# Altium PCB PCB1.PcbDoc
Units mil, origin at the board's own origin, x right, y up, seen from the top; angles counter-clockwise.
Board outline 3937.01 x 3937.01 mil, 2 copper layers (Top Layer, Bottom Layer); 21 components, 31 nets, 128 pads, 5 vias.
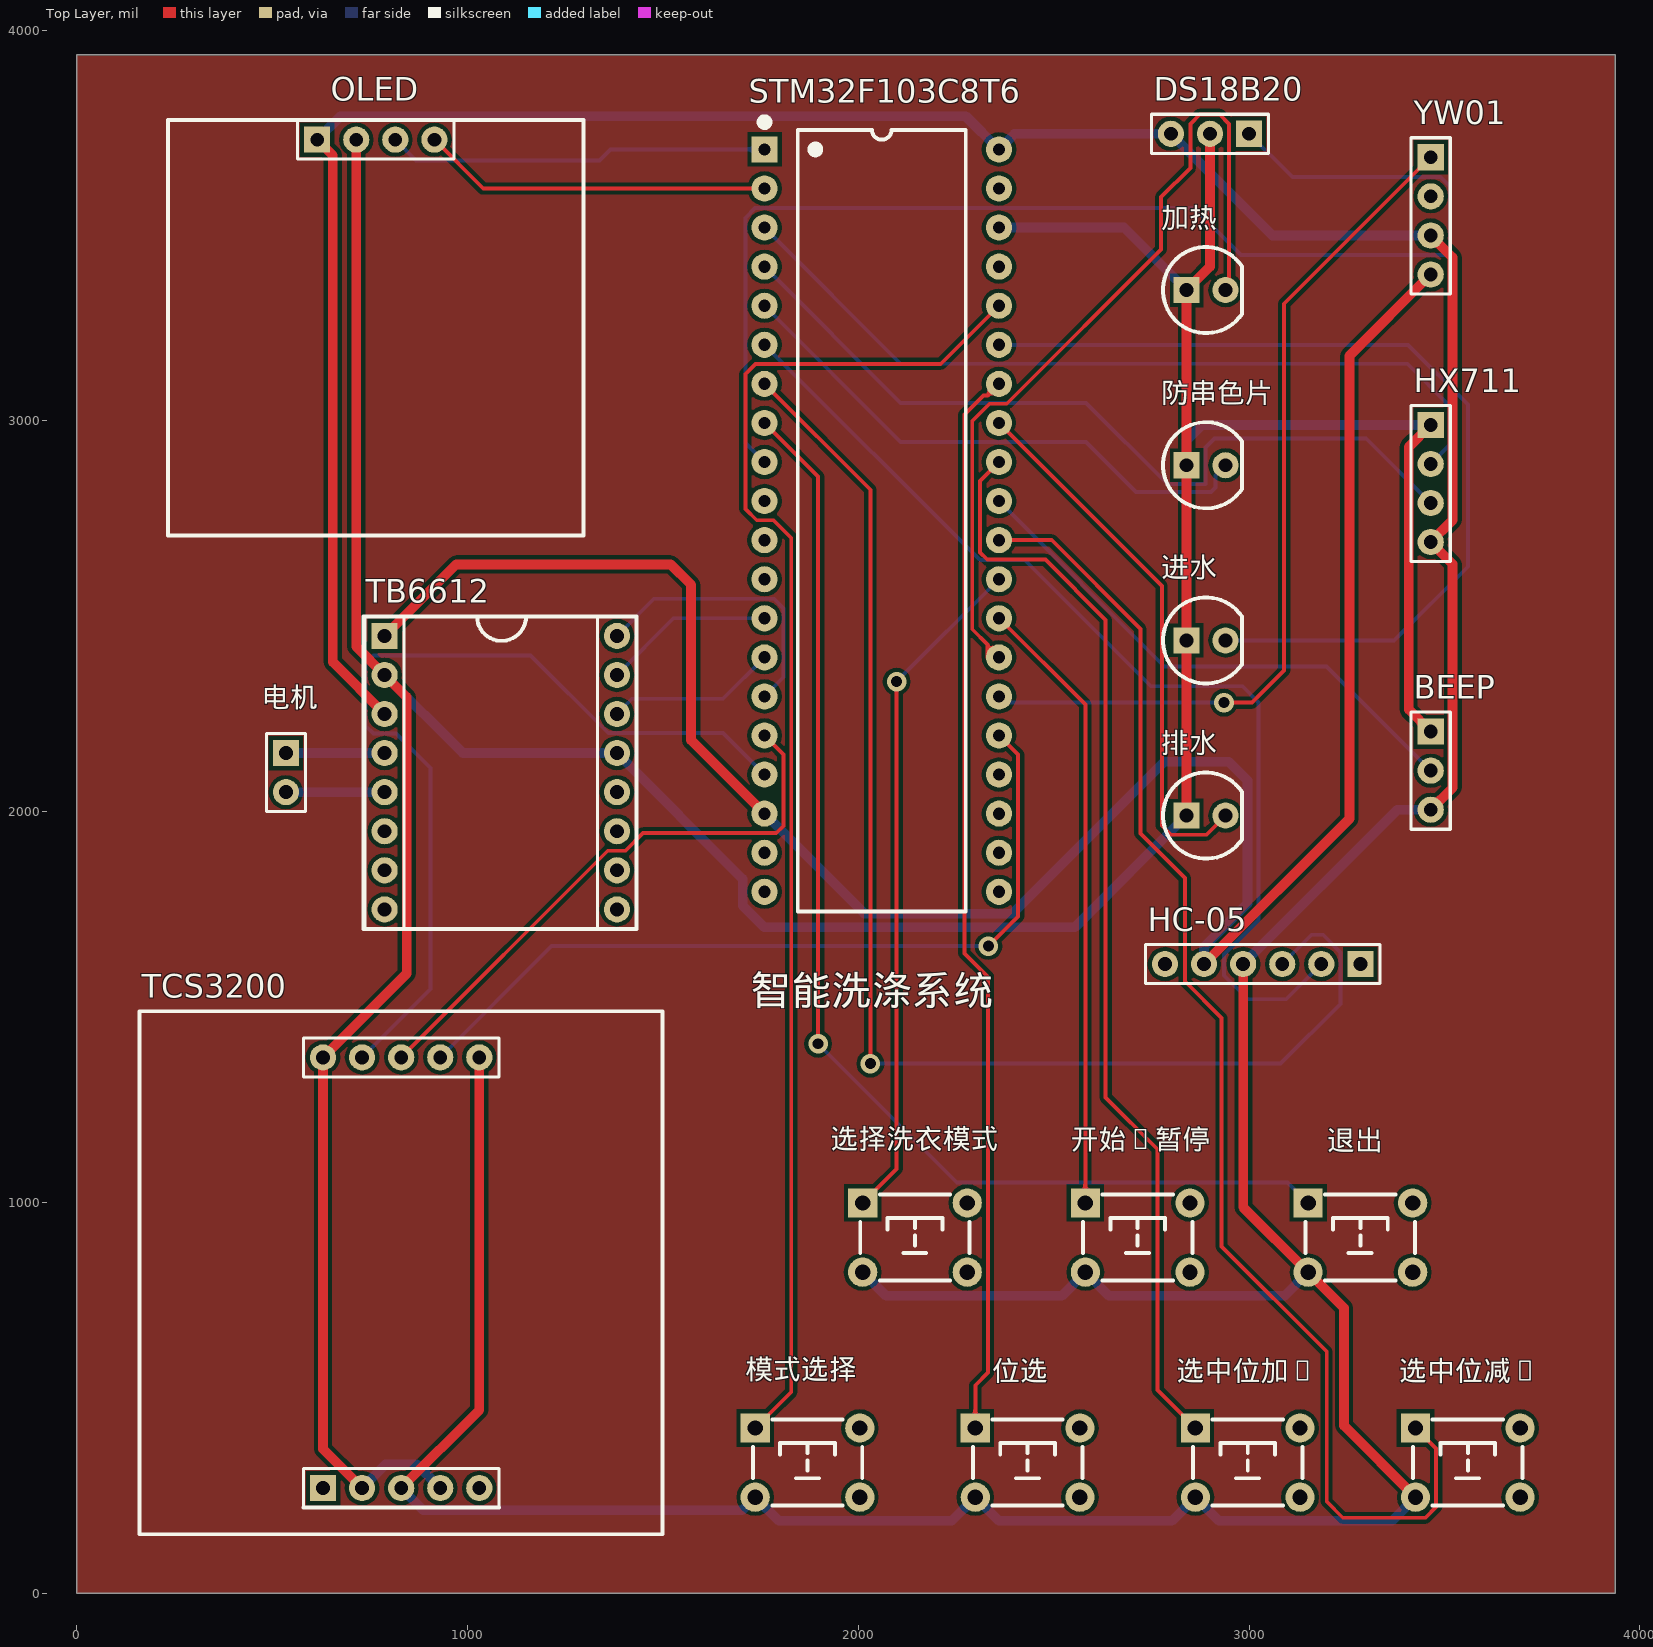
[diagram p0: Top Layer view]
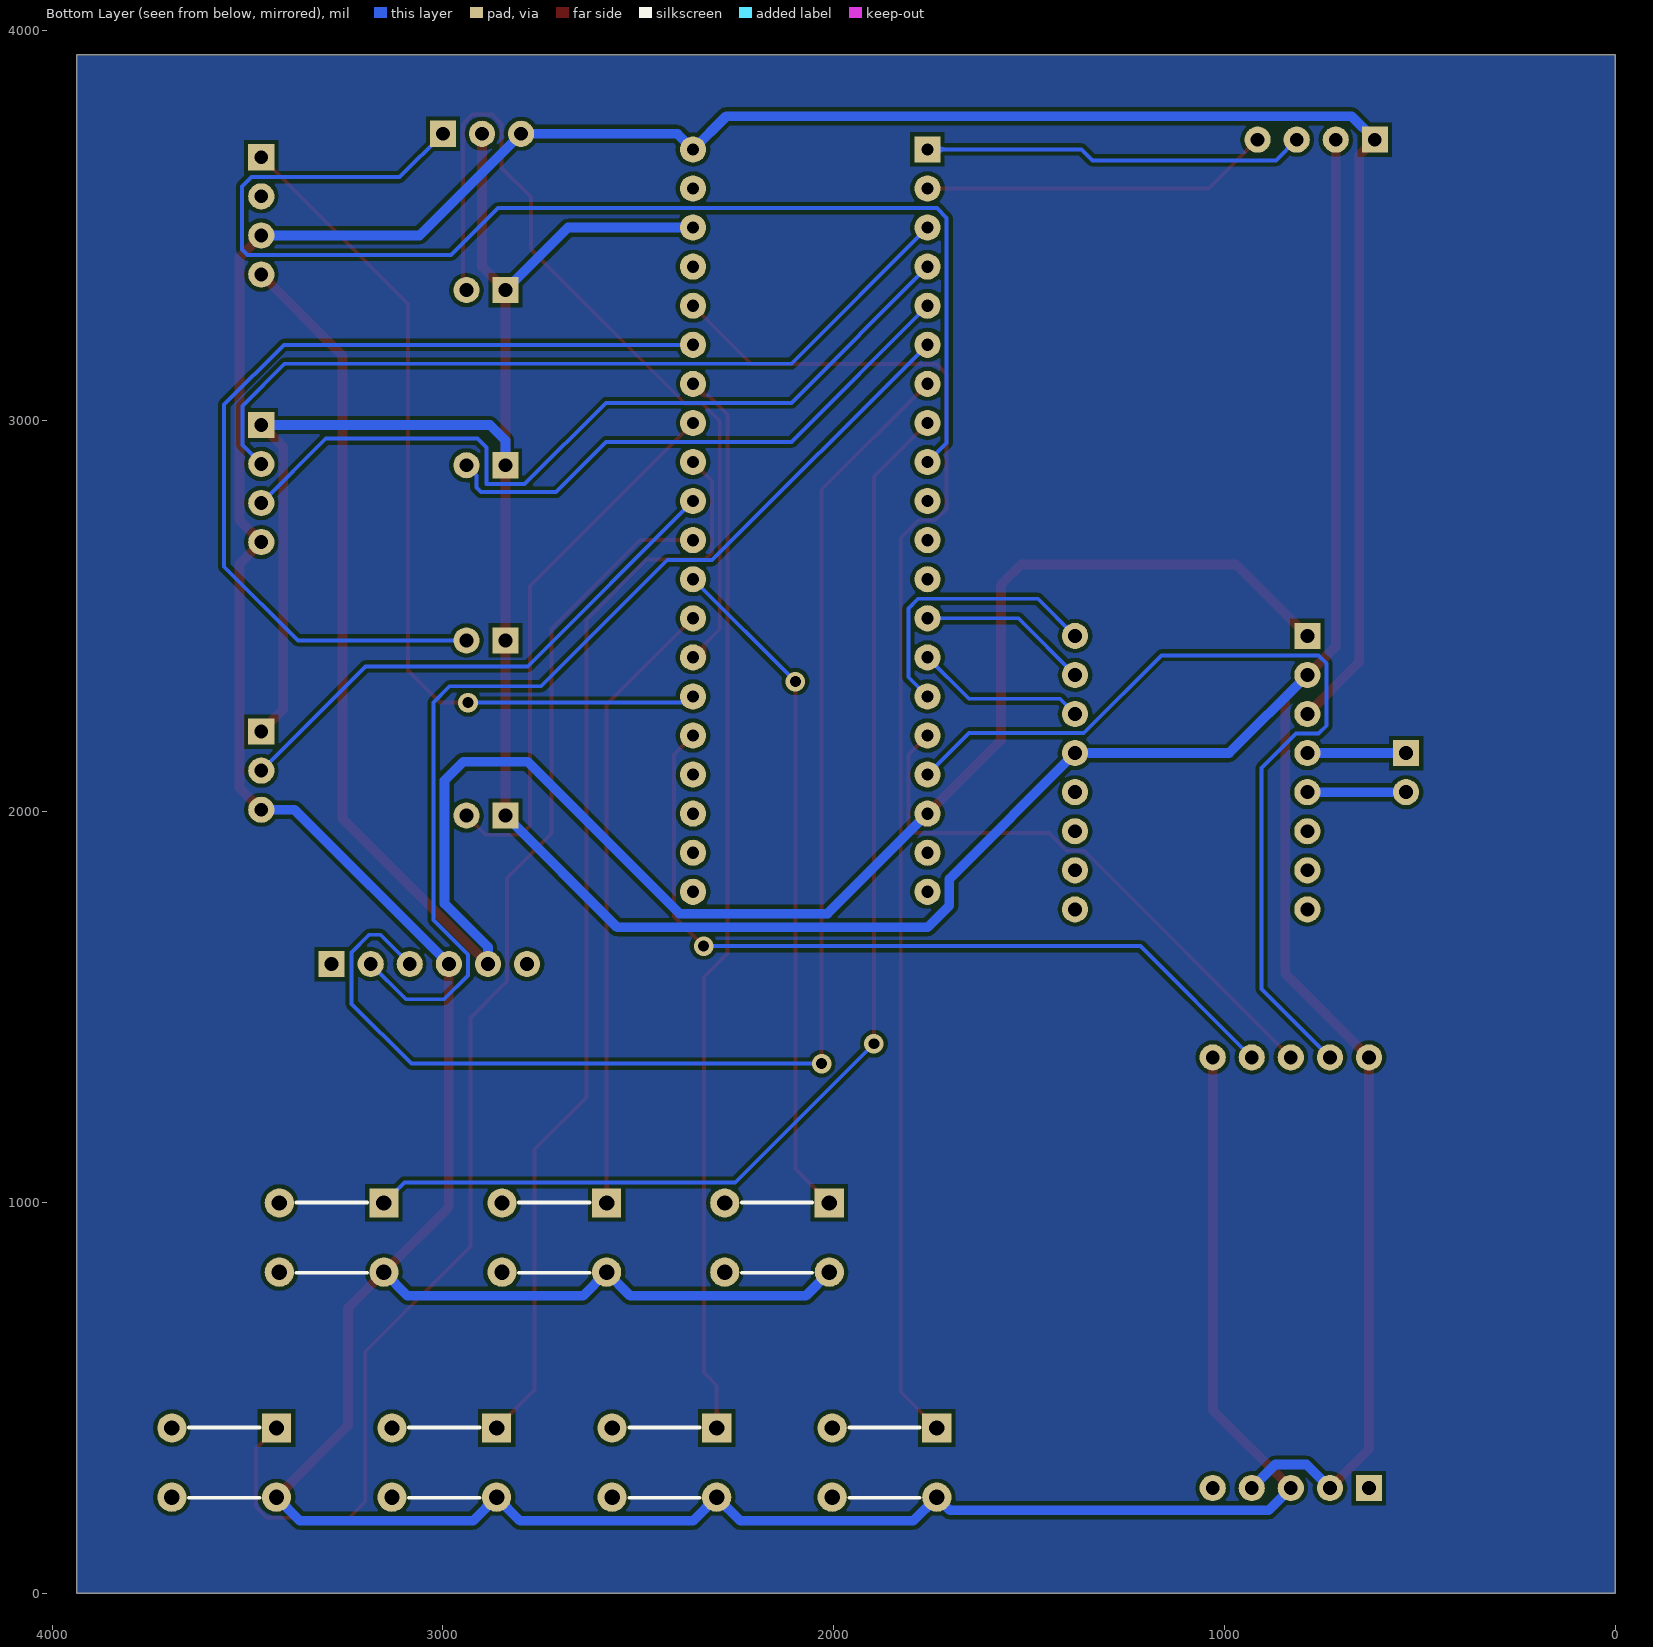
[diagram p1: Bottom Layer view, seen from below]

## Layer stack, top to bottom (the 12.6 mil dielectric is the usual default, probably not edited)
Top Solder: solder mask 0.4, Solder Resist, Dk 3.5
Top Layer: signal copper 1.4
Dielectric 1: dielectric 12.6, FR-4, Dk 4.8
Bottom Layer: signal copper 1.4
Bottom Solder: solder mask 0.4, Solder Resist, Dk 3.5

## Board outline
0,0 0,3937.01 3937.01,3937.01 3937.01,0

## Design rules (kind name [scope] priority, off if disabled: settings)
Clearance [All] p1: gap=10 ignorepadtopadclearanceinfootprint=FALSE except(0: Arc-Hole Track-Hole SMDPad-Hole THPad-Hole Via-Hole Fill-Hole Poly-Hole Region-Hole Text-Hole)
PolygonConnect [All] p1: connectstyle=Relief reliefconductorwidth=10 reliefentries=4 polygonreliefangle="90 Angle" airgapwidth=10
RoutingVias [All] p1: holewidth=28 width=50 viastyle="Through Hole" minholewidth=28 minwidth=50 maxholewidth=28 maxwidth=50
SolderMaskExpansion [All] p1: expansion=4
Width Width_Power_All [InNetClass('Power_All Nets')] p1: maxlimit=30 minlimit=20 preferedwidth=25 minimp=50.000000 maximp=50.000000 favimp=50.000000
Width [All] p2: maxlimit=10 minlimit=10 preferedwidth=10
30 further rules are at their usual default settings.

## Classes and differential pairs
net class "Power_All Nets": 3V3 5V GND NetB1_1 NetB1_2

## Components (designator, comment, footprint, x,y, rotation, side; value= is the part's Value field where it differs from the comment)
BEEP "BEEP" HDR2.54-M-LI-3P 3465,2105 r270 top
DS18B20 "?" HDR2.54-M-LI-3P 2900,3735 r180 top
HC-05 "HC-05" HDR2.54-M-LI-6P 3035,1610 r180 top
HX711 "HX711" HDR2.54-M-LI-4P 3465,2840 r270 top (schematic designator *)
OLED "OLED0.96" HDR2.54-M-LI-4P 765,3720 r0 top
STM32F103C8T6 "STM32F103C8T6" DIP40-600_MH 2060,2745 r0 top (schematic designator P1)
TB6612 "TB6612" HDR2.54-M-LI-8*2P 1085,2100 r270 top (schematic designator P2)
TCS3200 "TCS3200" HDR2.54-M-LI-5*2P 830,820 r0 top (schematic designator P3)
YW01 "YW01" HDR2.54-M-LI-4P 3465,3525 r270 top
位选 "TSW DIP-6x6" "TSW DIP-6*6*6" 2433.33,334 r0 top (schematic designator λѡ)
加热 "加热" "LED 5MM-R" 2890,3335 r0 top (schematic designator D1)
开始/暂停 "TSW DIP-6x6" "TSW DIP-6*6*6" 2715,910 r0 top
排水 "排水" "LED 5MM-R" 2890,1990 r0 top (schematic designator D4)
模式选择 "TSW DIP-6x6" "TSW DIP-6*6*6" 1870,334 r0 top
电机 "Motor" HDR2.54-LI-2P 535,2100 r270 top (schematic designator B1)
进水 "进水" "LED 5MM-R" 2890,2438.33 r0 top (schematic designator D3)
退出 "TSW DIP-6x6" "TSW DIP-6*6*6" 3285,910 r0 top
选中位减1 "TSW DIP-6x6" "TSW DIP-6*6*6" 3560,334 r0 top
选中位加1 "TSW DIP-6x6" "TSW DIP-6*6*6" 2996.67,334 r0 top
选择洗衣模式 "TSW DIP-6x6" "TSW DIP-6*6*6" 2145,910 r0 top
防串色片 "串色片" "LED 5MM-R" 2890,2886.67 r0 top (schematic designator D2)

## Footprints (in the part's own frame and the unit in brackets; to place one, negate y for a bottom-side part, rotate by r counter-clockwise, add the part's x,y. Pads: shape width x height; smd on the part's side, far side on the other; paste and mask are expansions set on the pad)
DIP40-600_MH [mm] "带底座 52*15.2*4mm(长宽高)"
  rect 1.7x1.7 hole 0.8: 1(-7.62,24.13)
  round 1.7 hole 0.8: 2(-7.62,21.59) 3(-7.62,19.05) 4(-7.62,16.51) 5(-7.62,13.97) 6(-7.62,11.43) 7(-7.62,8.89) 8(-7.62,6.35) 9(-7.62,3.81) 10(-7.62,1.27) 11(-7.62,-1.27) 12(-7.62,-3.81) 13(-7.62,-6.35) 14(-7.62,-8.89) 15(-7.62,-11.43) 16(-7.62,-13.97) 17(-7.62,-16.51) 18(-7.62,-19.05) 19(-7.62,-21.59) 20(-7.62,-24.13) 21(7.62,-24.13) 22(7.62,-21.59) 23(7.62,-19.05) 24(7.62,-16.51) 25(7.62,-13.97) 26(7.62,-11.43) 27(7.62,-8.89) 28(7.62,-6.35) 29(7.62,-3.81) 30(7.62,-1.27) 31(7.62,1.27) 32(7.62,3.81) 33(7.62,6.35) 34(7.62,8.89) 35(7.62,11.43) 36(7.62,13.97) 37(7.62,16.51) 38(7.62,19.05) 39(7.62,21.59) 40(7.62,24.13)
  silkscreen extent -7.87,-25.4 5.46,26.16, body extent -8.9,-26.18 8.9,26.18, height 8.3
HDR2.54-LI-2P [mm] "封装库来自淘宝卖家 ID：黄晶宝石"
  rect 1.7x1.7 hole 0.9: 1(-1.27,0)
  round 1.7 hole 0.9: 2(1.27,0)
  silkscreen extent -2.54,-1.27 2.54,1.27, body extent -2.54,-1.27 2.54,1.27, height 8.5
HDR2.54-M-LI-3P [mm] "排母，3脚   淘宝ID:黄晶宝石   店铺网址:https://shop463601444.taobao.com"
  rect 1.7x1.7 hole 0.9: 1(-2.54,0)
  round 1.7 hole 0.9: 2(0,0) 3(2.54,0)
  silkscreen extent -3.81,-1.27 3.81,1.27, body extent -3.81,-1.27 3.81,1.27, height 8.5
HDR2.54-M-LI-4P [mm] "排母，4脚  淘宝ID:黄晶宝石   店铺网址:https://shop463601444.taobao.com"
  rect 1.7x1.7 hole 0.9: 1(-3.81,0)
  round 1.7 hole 0.9: 2(-1.27,0) 3(1.27,0) 4(3.81,0)
  silkscreen extent -5.08,-1.27 5.08,1.27, body extent -5.08,-1.27 5.08,1.27, height 8.5
HDR2.54-M-LI-5*2P [mm]
  rect 1.7x1.7 hole 0.9: 1(-5.08,-14)
  round 1.7 hole 0.9: 2(-2.54,-14) 3(0,-14) 4(2.54,-14) 5(5.08,-14) 6(-5.08,14) 7(-2.54,14) 8(0,14) 9(2.54,14) 10(5.08,14)
  silkscreen extent -17,-17 17,17, body extent -6.35,-15.27 6.35,15.27, height 8.5
HDR2.54-M-LI-6P [mm] "排母，6脚  淘宝ID:黄晶宝石   店铺网址:https://shop463601444.taobao.com"
  rect 1.7x1.7 hole 0.9: 1(-6.35,0)
  round 1.7 hole 0.9: 2(-3.81,0) 3(-1.27,0) 4(1.27,0) 5(3.81,0) 6(6.35,0)
  silkscreen extent -7.62,-1.27 7.62,1.27, body extent -7.62,-1.27 7.62,1.27, height 8.5
HDR2.54-M-LI-8*2P [mm] "排母，8*2脚"
  rect 1.7x1.7 hole 0.9: 1(-8.89,-7.55)
  round 1.7 hole 0.9: 2(-6.35,-7.55) 3(-3.81,-7.55) 4(-1.27,-7.55) 5(1.27,-7.55) 6(3.81,-7.55) 7(6.35,-7.55) 8(8.89,-7.55) 9(-8.89,7.55) 10(-6.35,7.55) 11(-3.81,7.55) 12(-1.27,7.55) 13(1.27,7.55) 14(3.81,7.55) 15(6.35,7.55) 16(8.89,7.55)
  silkscreen extent -10.16,-8.92 10.16,8.82, body extent -10.16,-8.82 10.16,8.82, height 8.5
"LED 5MM-R" [mm] "红色5mm直插LED"
  rect 1.7x1.7 hole 0.9: 1(-1.27,0)
  round 1.7 hole 0.9: 2(1.27,0)
  silkscreen extent -2.8,-2.8 2.33,2.8, body extent -2.85,-2.85 2.45,2.85, height 8.75
"TSW DIP-6*6*6" [mm] "6*6*6mm"
  rect 1.9x1.9 hole 1: 1(-3.4,2.25)
  round 1.9 hole 1: 2(-3.4,-2.25) 3(3.4,-2.25) 4(3.4,2.25)
  silkscreen extent -3.56,-2.79 3.56,2.79, body extent -4.11,-3 4.11,3, height 5.95

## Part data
BEEP: "BEEP, 3-Pin"
DS18B20: library part DS18B20, "DS18B20, 3-Pin"
HC-05: "HC-05, 6-Pin"
HX711: "HX711,4-Pin"
OLED: library part OLED, "OLED0.96,4-Pin"
STM32F103C8T6: "最小系统板"
TB6612: library part TB66612, "TB66612,16-Pin"
TCS3200: library part PCS3200, "PCS3200, 10-Pin, Dual row"
YW01: "YW01,4-Pin"
位选 开始/暂停 模式选择 退出 选中位减1 选中位加1 选择洗衣模式: "直插6*6*5轻触开关"
加热 排水 进水 防串色片: library part LED, "Typical INFRARED GaAs LED"
电机: "Motor, General Kind"

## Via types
v1: diameter 50, hole 28, Top Layer to Bottom Layer, 5 vias

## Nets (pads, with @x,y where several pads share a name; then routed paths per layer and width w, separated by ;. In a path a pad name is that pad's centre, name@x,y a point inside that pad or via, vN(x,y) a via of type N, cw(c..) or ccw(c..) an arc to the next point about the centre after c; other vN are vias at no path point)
3V3: BEEP.1 DS18B20.2 HX711.1 OLED.2 STM32F103C8T6.38 TB6612.2 TB6612.12 TCS3200.2 TCS3200.4 TCS3200.6 加热.1 排水.1 进水.1 防串色片.1 | length 10215.2
  Top Layer w25: OLED.2 715,2422.76 TB6612.2 844,2293.76 844,1585.18 TCS3200.6 630,368.82 TCS3200.2 ; 排水.1 进水.1 防串色片.1 加热.1 2900,3395 DS18B20.2 ; BEEP.1 3409,2261 3409,2934 HX711.1
  Bottom Layer w25: TCS3200.2 790.18,329 869.82,329 TCS3200.4 ; TB6612.2 987.76,2150 TB6612.12 1704,1828.24 1704,1760 1759.97,1704.03 2554.03,1704.03 排水.1 ; STM32F103C8T6.38 2680,3495 加热.1 ; 防串色片.1 2840,2950 2880,2990 HX711.1
5V: HC-05.5 STM32F103C8T6.18 TB6612.1 YW01.4 | length 5589.7
  Top Layer w25: TB6612.1 970.76,2633 1520,2633 1572,2581 1572,2183 STM32F103C8T6.18 ; HC-05.5 3257,1982 3257,3167 YW01.4
  Bottom Layer w25: STM32F103C8T6.18 2015.97,1739.03 2395.03,1739.03 2784,2128 2948,2128 2996,2080 2996,1764.57 2885,1653.57 HC-05.5
GND: BEEP.3 DS18B20.3 HC-05.4 HX711.4 OLED.1 STM32F103C8T6.40 TB6612.3 TCS3200.3 TCS3200.10 YW01.3 位选.2 开始/暂停.2 模式选择.2 退出.2 选中位减1.2 选中位加1.2 选择洗衣模式.2 | length 13538.6
  Top Layer w25: OLED.1 655,3680 655,2382.76 TB6612.3 ; TCS3200.3 1030,468.82 TCS3200.10 ; HC-05.4 2985,987.56 退出.2 3243,729.56 3243,428.56 选中位减1.2 ; BEEP.3 3521,2061 3521,2634 HX711.4 3521,2746 3521,3419 YW01.3
  Bottom Layer w25: OLED.1 675,3780 2275,3780 STM32F103C8T6.40 2400,3735 DS18B20.3 3060,3475 YW01.3 ; TCS3200.3 886.82,212 1702.72,212 模式选择.2 1796.56,185 2239.06,185 位选.2 2359.89,185 2802.39,185 选中位加1.2 2923.23,185 3365.72,185 选中位减1.2 ; 选择洗衣模式.2 2071.56,761 2520.72,761 开始/暂停.2 2641.56,761 3090.72,761 退出.2 ; HC-05.4 3380,2005 BEEP.3
NetB1_1: TB6612.4 电机.1 | length 254.8
  Bottom Layer w25: 电机.1@535,2145 540,2150 TB6612.4
NetB1_2: TB6612.5 电机.2 | length 254.8
  Bottom Layer w25: 电机.2@535,2045 540,2050 TB6612.5
PA0: STM32F103C8T6.25 TCS3200.9 | length 2111.8
  Top Layer w10: v1(2333,1656) 2409,1732 2409,2146 STM32F103C8T6.25
  Bottom Layer w10: TCS3200.9 1214.82,1656 v1(2333,1656)
PA1: STM32F103C8T6.26 YW01.1 | length 2249.3
  Top Layer w10: v1(2936,2279) 3008,2279 3090,2361 3090,3300 YW01.1
  Bottom Layer w10: STM32F103C8T6.26 2360,2279 v1(2936,2279)
PA2: STM32F103C8T6.27 加热.2 | length 2215.3
  Top Layer w10: STM32F103C8T6.27 2331,2395 2331,2427.53 2291.53,2467 2291.53,3000 2335.53,3044 2380,3044 2775,3439 2775,3573 2850,3648 2850,3760 2874,3784 2925,3784 2949,3760 2949,3344 加热.2
PA3: STM32F103C8T6.28 开始/暂停.1 | length 1588
  Top Layer w10: STM32F103C8T6.28 2581.14,2273.86 开始/暂停.1
PA4: STM32F103C8T6.29 选择洗衣模式.1 | length 1740.9
  Top Layer w10: 选择洗衣模式.1 2098,1085.44 v1(2098,2333)
  Bottom Layer w10: v1(2098,2333) STM32F103C8T6.29
PA5: STM32F103C8T6.30 选中位减1.1 | length 3420.2
  Top Layer w10: STM32F103C8T6.30 2495,2695 2722,2468 2722,1944 2836,1830 2836,1566 2930,1472 2930,887 3199,618 3199,234 3240,193 3452,193 3479,220 3479,369.72 选中位减1.1
PA6: BEEP.2 STM32F103C8T6.31 | length 1390.8
  Bottom Layer w10: STM32F103C8T6.31 2783,2372 3198,2372 BEEP.2
PA7: STM32F103C8T6.32 选中位加1.1 | length 2808.1
  Top Layer w10: STM32F103C8T6.32 2311.53,2846.53 2311.53,2663.47 2330,2645 2479,2645 2633,2491 2633,1269 2766,1136 2766,519.39 选中位加1.1
PA8: STM32F103C8T6.5 防串色片.2 | length 1424.1
  Bottom Layer w10: STM32F103C8T6.5 2108.47,2946.53 2582.47,2946.53 2710.8,2818.2 2902.67,2818.2 2914.47,2830 2914.47,2861.13 防串色片.2
PA9: HC-05.2 STM32F103C8T6.6 | length 2690
  Bottom Layer w10: STM32F103C8T6.6 2311,2644 2426,2644 2749,2321 2983,2321 3024,2280 3024,1722.47 2936,1634.47 2936,1581 2997,1520 3095,1520 HC-05.2
PA10: HC-05.3 STM32F103C8T6.7 | length 3449.3
  Top Layer w10: STM32F103C8T6.7 2031,2824 v1(2031,1355)
  Bottom Layer w10: v1(2031,1355) 3081,1355 3234,1508 3234,1640 3189,1685 3160,1685 HC-05.3
PA11: STM32F103C8T6.8 退出.1 | length 3068.6
  Top Layer w10: STM32F103C8T6.8 1897,2858 v1(1897,1406)
  Bottom Layer w10: v1(1897,1406) 2252,1051 3098.72,1051 退出.1
PA12: DS18B20.1 STM32F103C8T6.9 | length 3245.1
  Bottom Layer w10: STM32F103C8T6.9 1711,2944 1711,3520 1736,3545 2859,3545 2979,3425 3500,3425 3514,3439 3514,3600 3490,3624 3111,3624 DS18B20.1
PB0: STM32F103C8T6.33 排水.2 | length 1396.6
  Top Layer w10: STM32F103C8T6.33 2777,2578 2777,1964 2800,1941 2891,1941 排水.2
PB1: STM32F103C8T6.34 位选.1 | length 2753.4
  Top Layer w10: 位选.1 2299.48,532 2332,564.52 2332,1577 2271.53,1637.47 2271.53,3016.42 2320,3064.88 2329.88,3064.88 STM32F103C8T6.34
PB5: STM32F103C8T6.13 TB6612.10 | length 437.8
  Bottom Layer w10: TB6612.10 1527.24,2495 STM32F103C8T6.13
PB6: STM32F103C8T6.14 TB6612.11 | length 437.8
  Bottom Layer w10: TB6612.11 1421.24,2289 1654,2289 STM32F103C8T6.14
PB7: STM32F103C8T6.15 TB6612.9 | length 721.8
  Bottom Layer w10: TB6612.9 1477.24,2545 1784,2545 1809,2520 1809,2344 STM32F103C8T6.15
PB8: STM32F103C8T6.16 TCS3200.8 | length 1475.4
  Top Layer w10: TCS3200.8 1358.82,1900 1404,1900 1449,1945 1790,1945 1808.47,1963.47 1808.47,2146.53 STM32F103C8T6.16
PB9: STM32F103C8T6.17 TCS3200.7 | length 2339.7
  Bottom Layer w10: TCS3200.7 905,1546.18 905,2112 817,2200 759,2200 739,2220 739,2380 759,2400 1161,2400 1360,2201 1654,2201 STM32F103C8T6.17
PB10: STM32F103C8T6.35 进水.2 | length 2376.7
  Bottom Layer w10: STM32F103C8T6.35 3407.32,3195 3560,3042.32 3560,2627 3371.33,2438.33 进水.2
PB11: STM32F103C8T6.36 模式选择.1 | length 3531
  Top Layer w10: 模式选择.1 1828.47,514.91 1828.47,2700.53 1783,2746 1740,2746 1711,2775 1711,3120 1737,3146 2211,3146 STM32F103C8T6.36
PB12: OLED.3 STM32F103C8T6.1 | length 978.6
  Bottom Layer w10: OLED.3 868,3667 1338,3667 1366,3695 STM32F103C8T6.1
PB13: OLED.4 STM32F103C8T6.2 | length 896.8
  Top Layer w10: OLED.4 1040,3595 STM32F103C8T6.2
PB14: HX711.2 STM32F103C8T6.3 | length 2111.1
  Bottom Layer w10: STM32F103C8T6.3 2108.47,3146.53 3405.4,3146.53 3513.47,3038.47 3513.47,2938.47 HX711.2
PB15: HX711.3 STM32F103C8T6.4 | length 2107.3
  Bottom Layer w10: STM32F103C8T6.4 2108.47,3046.53 2583.2,3046.53 2791.53,2838.2 2888.47,2838.2 2888.47,2932.06 2911.4,2955 3300,2955 HX711.3
pads on no net: HC-05.1 HC-05.6 STM32F103C8T6.10 STM32F103C8T6.11 STM32F103C8T6.12 STM32F103C8T6.19 STM32F103C8T6.20 STM32F103C8T6.21 STM32F103C8T6.22 STM32F103C8T6.23 STM32F103C8T6.24 STM32F103C8T6.37 STM32F103C8T6.39 TB6612.6 TB6612.7 TB6612.8 TB6612.13 TB6612.14 TB6612.15 TB6612.16 TCS3200.1 TCS3200.5 YW01.2 位选.3 位选.4 开始/暂停.3 开始/暂停.4 模式选择.3 模式选择.4 退出.3 退出.4 选中位减1.3 选中位减1.4 选中位加1.3 选中位加1.4 选择洗衣模式.3 选择洗衣模式.4

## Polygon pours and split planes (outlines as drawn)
no net on Top Layer (solid, pour order 0): 0,3935 3935,3935 3935,0 0,0
no net on Bottom Layer (solid, pour order 2): 0,3935 3935,3935 3935,0 0,0

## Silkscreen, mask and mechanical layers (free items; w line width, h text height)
Top Overlay:
  lines w10: 233.5,2707.01 1296.5,2707.01 1296.5,3770 233.5,3770 233.5,2707.01
  text "智能洗涤系统" at 1725,1480 h130
Mechanical 1:
  the board outline again, w10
